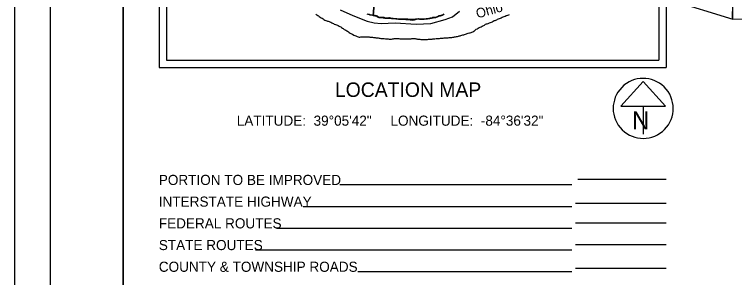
# Model space of a CAD drawing. Extents: x 0 to 34, y -2 to 22.
# Drawn here: x 0 to 9.95, y 11.1 to 14.73 of the extents above; entities that cross this region are included whole.
import ezdxf

# ---------------------------------------------------------------- set-up
doc = ezdxf.new("R2010")
doc.units = 0
for name, color, linetype in [('GM_X_Major_River', 7, 'Continuous'), ('GM_X_Major_River_Text', 7, 'Continuous'), ('GM_X_Rail_Line', 7, 'Continuous'), ('GM_X_Section', 7, 'Continuous'), ('SH_Border', 7, 'Continuous'), ('SH_Cut_Line', 7, 'Continuous'), ('SH_Data', 7, 'Continuous'), ('SH_Text', 7, 'Continuous')]:
    doc.layers.add(name, color=color, linetype=linetype)

msp = doc.modelspace()

# ---------------------------------------------------------------- linework, layer by layer
at = {"layer": 'GM_X_Major_River'}
for points in [[(4.1651, 14.7366), (4.1779, 14.728), (4.191, 14.7202), (4.2012, 14.7132), (4.2109, 14.7074), (4.2233, 14.6981), (4.2379, 14.688), (4.2496, 14.6802), (4.2635, 14.6713), (4.2759, 14.6624), (4.2898, 14.6545), (4.3033, 14.6498), (4.3139, 14.6462), (4.3249, 14.643), (4.3358, 14.639), (4.3475, 14.635), (4.3573, 14.6311), (4.3682, 14.6264), (4.3825, 14.6193), (4.3957, 14.6127), (4.4059, 14.6072), (4.4187, 14.6009), (4.4341, 14.5942), (4.4473, 14.5887), (4.4605, 14.5843), (4.4733, 14.5796), (4.4865, 14.574), (4.4963, 14.5682), (4.5072, 14.5616), (4.5181, 14.5542), (4.5327, 14.546), (4.5425, 14.5383), (4.5564, 14.5278), (4.5661, 14.5223), (4.5767, 14.5165), (4.5902, 14.5087), (4.6022, 14.5024), (4.6131, 14.4954), (4.6236, 14.4865), (4.6371, 14.4768), (4.6477, 14.4714), (4.6578, 14.467), (4.6686, 14.462)], [(5.6287, 14.663), (5.6116, 14.663), (5.5999, 14.6648), (5.5863, 14.6686), (5.5727, 14.6705), (5.5605, 14.6674), (5.5467, 14.6635), (5.5337, 14.6593), (5.5222, 14.655), (5.5093, 14.6535), (5.4998, 14.6522), (5.485, 14.6529), (5.4725, 14.6548), (5.4604, 14.657), (5.4472, 14.6592), (5.4362, 14.6602), (5.4252, 14.6609), (5.4131, 14.6612), (5.3998, 14.6619), (5.3873, 14.6622), (5.3745, 14.6629), (5.3608, 14.6637), (5.351, 14.6643), (5.3392, 14.665), (5.3256, 14.6657), (5.3074, 14.6661), (5.2979, 14.6668), (5.2854, 14.6678), (5.2737, 14.6696), (5.2623, 14.6711), (5.2457, 14.6726), (5.2355, 14.674), (5.223, 14.6747), (5.212, 14.6754), (5.2014, 14.6756), (5.1881, 14.6764), (5.1749, 14.6786), (5.1654, 14.6784), (5.1555, 14.6776), (5.1418, 14.6768), (5.132, 14.6766), (5.1221, 14.678), (5.1123, 14.6802), (5.0999, 14.6828), (5.0855, 14.6854), (5.076, 14.6852), (5.0658, 14.6863), (5.0541, 14.6881), (5.0396, 14.6869), (5.0272, 14.6903), (5.0171, 14.6958), (5.004, 14.7034), (4.9924, 14.7086), (4.9826, 14.7115), (4.9728, 14.7137), (4.9603, 14.7162), (4.9501, 14.7188), (4.9335, 14.7218), (4.9229, 14.7236), (4.912, 14.7258), (4.9022, 14.7283), (4.8856, 14.7322), (4.8702, 14.7379)], [(5.9288, 14.7404), (5.9221, 14.7284), (5.9074, 14.7178), (5.8948, 14.7136), (5.8818, 14.712), (5.8711, 14.7092), (5.8596, 14.705), (5.8481, 14.6992), (5.8381, 14.6945), (5.827, 14.691), (5.816, 14.6879), (5.8034, 14.6867), (5.7886, 14.6848), (5.7783, 14.6831), (5.7684, 14.6807), (5.7558, 14.6776), (5.7458, 14.6756), (5.7336, 14.6732), (5.7218, 14.6716), (5.7074, 14.6701), (5.6971, 14.6692), (5.6796, 14.6678), (5.6644, 14.6663), (5.6545, 14.665), (5.6408, 14.6642), (5.6287, 14.663)], [(6.7903, 14.7173), (6.8002, 14.7204), (6.8159, 14.7261), (6.8282, 14.7307), (6.84, 14.735)], [(5.5011, 14.3999), (5.511, 14.4), (5.5345, 14.3995), (5.545, 14.3973), (5.5579, 14.3947), (5.5681, 14.3929), (5.5783, 14.3915), (5.5885, 14.3909), (5.5991, 14.3899), (5.6131, 14.3888), (5.6298, 14.3864), (5.6438, 14.3861), (5.6612, 14.3856), (5.6738, 14.3861), (5.6844, 14.3866), (5.6951, 14.3882), (5.7061, 14.3894), (5.7175, 14.3907), (5.7289, 14.3911), (5.7433, 14.3919), (5.7563, 14.3927), (5.7692, 14.3939), (5.781, 14.3951), (5.7955, 14.3971), (5.8088, 14.399), (5.8244, 14.4009), (5.8407, 14.4024), (5.8559, 14.4027), (5.8696, 14.4032), (5.8855, 14.4039), (5.8954, 14.4048), (5.9099, 14.4056), (5.924, 14.4079), (5.9377, 14.4094), (5.9532, 14.4105), (5.9673, 14.4113), (5.9802, 14.4121), (5.9928, 14.4126), (6.0034, 14.4134), (6.0167, 14.4154), (6.0293, 14.4158), (6.043, 14.4174), (6.0575, 14.4208), (6.0681, 14.4217), (6.0799, 14.4233), (6.0906, 14.4249), (6.1047, 14.4272), (6.1192, 14.4306), (6.1321, 14.433), (6.1432, 14.4365), (6.1562, 14.4403), (6.1665, 14.4423), (6.1799, 14.4462), (6.1937, 14.4504), (6.207, 14.4542), (6.2185, 14.4573), (6.2296, 14.4612), (6.2449, 14.4658), (6.2548, 14.4697), (6.2663, 14.4732), (6.2843, 14.4777), (6.2957, 14.4812), (6.3079, 14.4843), (6.3194, 14.4886), (6.3317, 14.494), (6.3444, 14.502), (6.3541, 14.5089), (6.3677, 14.5215), (6.3792, 14.5288), (6.3938, 14.5364), (6.4062, 14.544), (6.4201, 14.5528), (6.4312, 14.5578), (6.4446, 14.5639), (6.4596, 14.5708), (6.4703, 14.5754), (6.483, 14.5801), (6.493, 14.5866), (6.5062, 14.5977), (6.52, 14.6038), (6.5295, 14.6058), (6.5429, 14.6093), (6.5536, 14.6139), (6.5632, 14.619), (6.5907, 14.6251), (6.6015, 14.6306), (6.6146, 14.6412), (6.6262, 14.6485), (6.6388, 14.6509), (6.651, 14.6536), (6.6637, 14.6601), (6.6744, 14.6663), (6.6867, 14.6732), (6.7005, 14.6782), (6.7116, 14.6824), (6.7235, 14.6874), (6.737, 14.6943), (6.7523, 14.7019), (6.7627, 14.7062), (6.7769, 14.7119), (6.7903, 14.7173)], [(4.6686, 14.462), (4.6884, 14.4466), (4.7015, 14.4409), (4.714, 14.4372), (4.7256, 14.4339), (4.7354, 14.431), (4.7485, 14.4242), (4.7633, 14.4212), (4.7731, 14.4213), (4.7845, 14.4222), (4.7944, 14.423), (4.8074, 14.4242), (4.8206, 14.4247), (4.8354, 14.4247), (4.8499, 14.4254), (4.8719, 14.4249), (4.8851, 14.4238), (4.8988, 14.4227), (4.9113, 14.422), (4.9211, 14.4214), (4.9332, 14.4195), (4.9476, 14.4177), (4.9589, 14.417), (4.9695, 14.4156), (4.982, 14.4138), (4.9941, 14.4123), (5.0043, 14.4117), (5.0153, 14.4103), (5.0251, 14.4085), (5.038, 14.4063), (5.0489, 14.4041), (5.0595, 14.4023), (5.0735, 14.4001), (5.086, 14.3998), (5.0993, 14.3998), (5.1091, 14.3992), (5.125, 14.3976), (5.139, 14.3965), (5.15, 14.3951), (5.1633, 14.3948), (5.1762, 14.3937), (5.1864, 14.3931), (5.1966, 14.3928), (5.2092, 14.3944), (5.2233, 14.3971), (5.2343, 14.3983), (5.245, 14.3992), (5.2552, 14.3997), (5.267, 14.3994), (5.2772, 14.3995), (5.2886, 14.3996), (5.3004, 14.3997), (5.3114, 14.3994), (5.3216, 14.3984), (5.336, 14.3965), (5.3469, 14.3958), (5.3599, 14.397), (5.3735, 14.3974), (5.3857, 14.3979), (5.3986, 14.3979), (5.4081, 14.3985), (5.4244, 14.3984), (5.4373, 14.3981), (5.4479, 14.3982), (5.4574, 14.3984), (5.4692, 14.3984), (5.4802, 14.3989), (5.4905, 14.3998), (5.5011, 14.3999)]]:
    msp.add_lwpolyline(points, dxfattribs=at)
at = {"layer": 'GM_X_Rail_Line'}
msp.add_lwpolyline([(4.5005, 14.7957), (4.6757, 14.7172), (4.8729, 14.6413), (4.9705, 14.6171), (5.0672, 14.6072), (5.26, 14.6167), (5.5499, 14.6), (5.7525, 14.6107), (5.9498, 14.6618), (6.0485, 14.702), (6.1464, 14.7771)], dxfattribs=at)
at = {"layer": 'GM_X_Section'}
for points in [[(5.0363, 15.7105), (4.955, 14.7206), (4.9346, 14.7249), (4.9143, 14.7307), (4.8944, 14.7375)], [(5.9259, 14.7378), (5.9239, 14.7337), (5.9185, 14.7285), (5.9112, 14.7241), (5.9032, 14.7217), (5.8879, 14.7186), (5.8754, 14.7166), (5.8659, 14.7153), (5.8617, 14.7139), (5.8548, 14.7091), (5.8463, 14.7033), (5.8409, 14.7007), (5.8246, 14.6969), (5.7949, 14.6919), (5.7767, 14.6897), (5.7709, 14.6876), (5.761, 14.684), (5.7568, 14.683), (5.7477, 14.6832), (5.7405, 14.6822), (5.7234, 14.6777), (5.7093, 14.6753), (5.6998, 14.6752), (5.6876, 14.672), (5.6671, 14.6702), (5.6546, 14.6698), (5.6356, 14.6691), (5.6186, 14.6691), (5.6069, 14.6693), (5.5974, 14.6703), (5.5835, 14.674), (5.5755, 14.6746), (5.5379, 14.6671), (5.5253, 14.6644), (5.5147, 14.6631), (5.4757, 14.6648), (5.436, 14.668), (5.4091, 14.667), (5.3879, 14.6679), (5.3107, 14.6704), (5.28, 14.6723), (5.2547, 14.6732), (5.2293, 14.6761), (5.1995, 14.6802), (5.1784, 14.6856), (5.1708, 14.6858), (5.1458, 14.6833), (5.1329, 14.6821), (5.1253, 14.6826), (5.1152, 14.6863), (5.1065, 14.6895), (5.0876, 14.6899), (5.0778, 14.6917), (5.071, 14.6934), (5.0604, 14.6936), (5.0513, 14.6927), (5.0415, 14.6936), (5.0332, 14.6969), (5.0231, 14.7024), (5.0142, 14.7087), (5.001, 14.7131), (4.9825, 14.7177), (4.955, 14.7206), (5.0363, 15.7105)]]:
    msp.add_lwpolyline(points, dxfattribs=at)
at = {"layer": 'SH_Border'}
for points in [[(0.5, 21.5), (1.5, 21.5), (1.5, 0.5), (0.5, 0.5)], [(1.5, 21.5), (33.5, 21.5), (33.5, 0.5), (1.5, 0.5)]]:
    msp.add_lwpolyline(points, close=True, dxfattribs=at)
at = {"layer": 'SH_Cut_Line'}
msp.add_lwpolyline([(0, 0), (34, 0), (34, 22), (0, 22)], close=True, dxfattribs=at)
msp.add_lwpolyline([(4.5005, 14.7957), (4.6757, 14.7172), (4.8729, 14.6413), (4.9705, 14.6171), (5.0672, 14.6072), (5.26, 14.6167), (5.5499, 14.6), (5.7525, 14.6107), (5.9498, 14.6618), (6.0485, 14.702), (6.1464, 14.7771)], dxfattribs=at)
at = {"layer": 'SH_Data'}
for p, q in [((2, 21), (2, 14)), ((9, 21), (9, 14)), ((2.1, 20.9), (2.1, 14.1)), ((8.9, 20.9), (8.9, 14.1)), ((2.1, 14.1), (8.9, 14.1)), ((2.1, 14.1), (2.1, 14.1)), ((2, 14), (9, 14)), ((8.6845, 13.8091), (8.3769, 13.4678)), ((8.9921, 13.4678), (8.6845, 13.8091)), ((8.3769, 13.4678), (8.9921, 13.4678)), ((8.6845, 13.4678), (8.6845, 13.0811)), ((8.6845, 13.4353), (8.6845, 13.4353)), ((8.6845, 13.4353), (8.6845, 13.4353)), ((7.7827, 12.4553), (9, 12.4553)), ((7.7, 12.3767), (4.4937, 12.3767)), ((7.7, 12.0767), (3.9895, 12.0767)), ((9, 12.1207), (7.75, 12.1207)), ((9, 11.8491), (7.75, 11.8491)), ((7.7, 11.7767), (3.6192, 11.7767)), ((9, 11.5491), (7.75, 11.5491)), ((7.7, 11.4767), (3.3288, 11.4767)), ((7.7, 11.1767), (4.7452, 11.1767)), ((9, 11.2223), (7.75, 11.2223))]:
    msp.add_line(p, q, dxfattribs=at)
msp.add_lwpolyline([(5.5742, 16.0105), (9.9214, 14.669), (9.9247, 15.1051)], close=True, dxfattribs=at)
msp.add_arc((8.6845, 13.4353), 0.4148, 129.77984, 129.76332, dxfattribs=at)
at = {"layer": 'SH_Text'}
msp.add_lwpolyline([(9.9251, 15.1052), (11.4435, 15.0832), (11.4372, 14.6485), (9.9188, 14.6705)], close=True, dxfattribs=at)

# ---------------------------------------------------------------- texts
at = {"layer": 'GM_X_Major_River_Text'}
msp.add_text('Ohio', height=0.13257, rotation=16.00103, dxfattribs=at).set_placement((6.3962, 14.6775))
at = {"layer": 'SH_Data'}
msp.add_text('N', height=0.25, dxfattribs=at).set_placement((8.5292, 13.144))
at = {"layer": 'SH_Text'}
for s, height, p in [('LOCATION MAP', 0.2, (4.4269, 13.5938)), ('LATITUDE:  39°05\'42"     LONGITUDE:  -84°36\'32"', 0.14, (3.071, 13.1959)), ('PORTION TO BE IMPROVED', 0.14, (1.9944, 12.3767)), ('INTERSTATE HIGHWAY', 0.14, (1.9944, 12.0767)), ('FEDERAL ROUTES', 0.14, (1.9944, 11.7767)), ('STATE ROUTES', 0.14, (1.9944, 11.4767)), ('COUNTY & TOWNSHIP ROADS', 0.14, (1.9944, 11.1767))]:
    msp.add_text(s, height=height, dxfattribs=at).set_placement(p)

doc.saveas('drawing.dxf')
